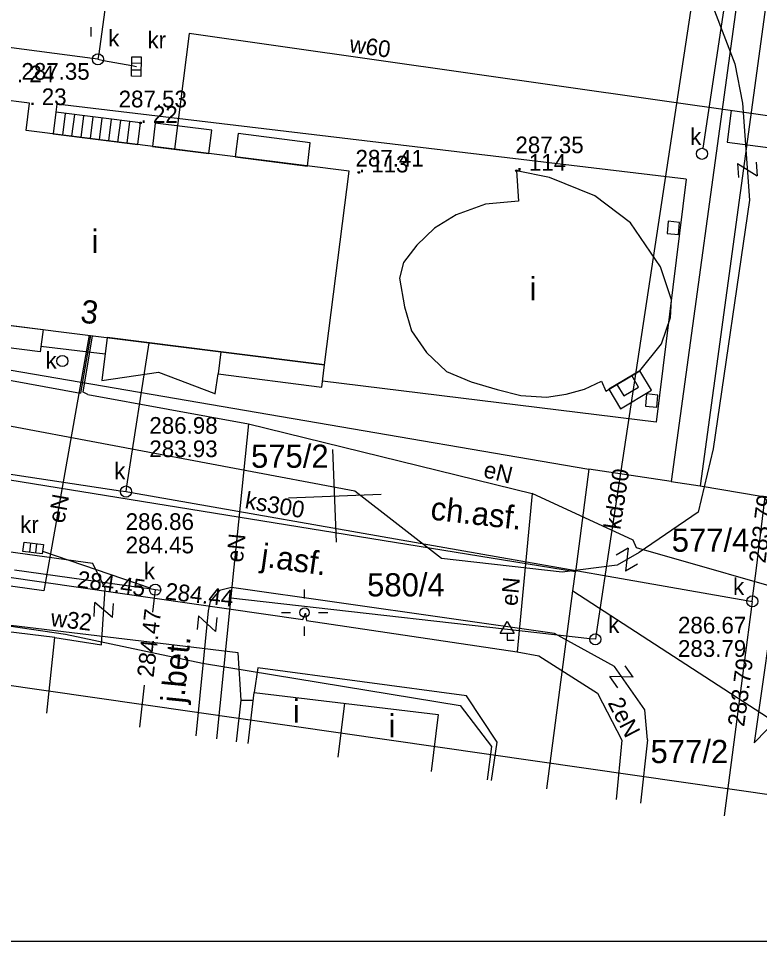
# Model space of a CAD drawing. Extents: x 4632591 to 4651936, y 5351032 to 5369988.
# Drawn here: x 4642770.86 to 4642810.82, y 5360025.34 to 5360075.11 of the extents above; entities that cross this region are included whole.
import ezdxf

# ---------------------------------------------------------------- set-up
doc = ezdxf.new("R2010")
doc.units = 0
for name, color, linetype in [('EADPD_238', 7, 'Continuous'), ('EBUPO_314', 7, 'Continuous'), ('EBUPP_312', 7, 'Continuous'), ('EBUPP_316', 7, 'Continuous'), ('EDTTS_991', 7, 'Continuous'), ('EDZPD_211', 7, 'Continuous'), ('EDZPD_219', 7, 'Continuous'), ('SDRPK_422', 7, 'Continuous'), ('SDRPK_423', 7, 'Continuous'), ('SDRPK_432', 7, 'Continuous'), ('SDRPZ_407', 7, 'Continuous'), ('UEEPA_510', 7, 'Continuous'), ('UEEPO_585', 7, 'Continuous'), ('UEETA_515', 7, 'Continuous'), ('UKKPA_506', 7, 'Continuous'), ('UKKPA_509', 7, 'Continuous'), ('UKKPO_582', 7, 'Continuous'), ('UWWPO_581', 7, 'Continuous'), ('Warstwa 40', 7, 'Continuous'), ('Warstwa 50', 7, 'Continuous'), ('Warstwa 62', 7, 'Continuous'), ('WUKPS_403', 7, 'Continuous')]:
    doc.layers.add(name, color=color, linetype=linetype)

msp = doc.modelspace()

# ---------------------------------------------------------------- linework, layer by layer
at = {"layer": 'EBUPO_314'}
for points in [[(4642806.854, 5360066.446), (4642772.935, 5360070.496), (4642772.882, 5360070.055)], [(4642806.854, 5360066.446), (4642805.234, 5360053.335), (4642787.255, 5360055.555)], [(4642775.531, 5360057.003), (4642772.073, 5360057.43)]]:
    msp.add_lwpolyline(points, dxfattribs=at)
at = {"layer": 'EBUPP_312'}
for p, q in [((4642771.462, 5360070.537), (4642765.12, 5360071.336)), ((4642771.277, 5360069.068), (4642771.462, 5360070.537)), ((4642788.682, 5360066.873), (4642771.277, 5360069.068)), ((4642787.365, 5360056.43), (4642788.682, 5360066.873)), ((4642769.194, 5360058.721), (4642787.365, 5360056.43))]:
    msp.add_line(p, q, dxfattribs=at)
for points in [[(4642867.168, 5360325.869), (4642867.168, 5360025.339), (4642701.152, 5360025.339), (4642701.152, 5360349.707), (4642867.168, 5360349.707), (4642867.168, 5360324.166)], [(4642772.396, 5360037.653), (4642772.817, 5360041.74), (4642764.24, 5360042.78), (4642763.711, 5360038.969)]]:
    msp.add_lwpolyline(points, dxfattribs=at)
for points in [[(4642797.71, 5360066.9), (4642797.816, 5360065.261), (4642796.034, 5360065.101), (4642794.464, 5360064.516), (4642793.293, 5360063.797), (4642792.336, 5360062.893), (4642791.617, 5360061.962), (4642791.404, 5360061.11), (4642791.67, 5360059.567), (4642792.043, 5360058.264), (4642792.868, 5360057.093), (4642793.932, 5360056.082), (4642795.262, 5360055.523), (4642796.672, 5360055.098), (4642797.949, 5360054.778), (4642799.333, 5360054.699), (4642800.397, 5360054.858), (4642801.381, 5360055.124), (4642802.286, 5360055.55), (4642802.525, 5360055.018), (4642804.361, 5360056.109), (4642805.532, 5360057.572), (4642806.011, 5360058.982), (4642806.064, 5360059.94), (4642805.478, 5360061.722), (4642803.856, 5360064.09), (4642801.94, 5360065.553), (4642799.492, 5360066.538)], [(4642805.829, 5360063.513), (4642806.439, 5360063.455), (4642806.501, 5360064.116), (4642805.891, 5360064.173)], [(4642804.665, 5360054.202), (4642805.275, 5360054.145), (4642805.337, 5360054.806), (4642804.727, 5360054.863)]]:
    msp.add_lwpolyline(points, close=True, dxfattribs=at)
at = {"layer": 'EBUPP_316'}
for p, q in [((4642772.882, 5360070.055), (4642772.735, 5360068.884)), ((4642777.44, 5360069.48), (4642772.882, 5360070.055)), ((4642773.378, 5360069.992), (4642773.231, 5360068.821)), ((4642773.874, 5360069.93), (4642773.727, 5360068.759)), ((4642774.37, 5360069.867), (4642774.223, 5360068.696)), ((4642774.866, 5360069.804), (4642774.719, 5360068.634)), ((4642775.363, 5360069.742), (4642775.215, 5360068.571)), ((4642775.859, 5360069.679), (4642775.711, 5360068.509)), ((4642776.355, 5360069.617), (4642776.207, 5360068.446)), ((4642776.851, 5360069.554), (4642776.703, 5360068.383)), ((4642777.292, 5360068.309), (4642777.44, 5360069.48)), ((4642772.735, 5360068.884), (4642777.292, 5360068.309)), ((4642804.361, 5360056.109), (4642802.696, 5360055.119)), ((4642804.298, 5360055.235), (4642803.931, 5360055.853)), ((4642804.984, 5360055.061), (4642804.361, 5360056.109)), ((4642803.126, 5360055.375), (4642803.493, 5360054.757)), ((4642803.493, 5360054.757), (4642804.298, 5360055.235)), ((4642802.696, 5360055.119), (4642803.318, 5360054.071)), ((4642803.318, 5360054.071), (4642804.984, 5360055.061)), ((4642783.238, 5360036.01), (4642783.573, 5360038.775)), ((4642783.573, 5360038.775), (4642793.488, 5360037.576)), ((4642788.098, 5360035.274), (4642788.451, 5360038.185)), ((4642793.488, 5360037.576), (4642793.117, 5360034.513))]:
    msp.add_line(p, q, dxfattribs=at)
for points in [[(4642778.079, 5360068.21), (4642781.131, 5360067.825), (4642781.29, 5360069.086), (4642778.238, 5360069.471)], [(4642782.553, 5360067.646), (4642786.438, 5360067.156), (4642786.596, 5360068.41), (4642782.711, 5360068.9)], [(4642769.194, 5360058.721), (4642772.188, 5360058.344), (4642772.036, 5360057.139), (4642769.042, 5360057.517)], [(4642787.365, 5360056.43), (4642781.773, 5360057.135), (4642781.623, 5360055.941), (4642787.215, 5360055.236)]]:
    msp.add_lwpolyline(points, close=True, dxfattribs=at)
msp.add_lwpolyline([(4642781.773, 5360057.135), (4642775.646, 5360057.908), (4642775.353, 5360055.591), (4642778.413, 5360056.044), (4642781.393, 5360054.9), (4642781.466, 5360054.873), (4642781.623, 5360055.941)], dxfattribs=at)
at = {"layer": 'EDTTS_991'}
for p, q in [((4642809.63, 5360067.293), (4642809.685, 5360066.545)), ((4642809.63, 5360067.293), (4642810.682, 5360066.619)), ((4642810.627, 5360067.367), (4642810.682, 5360066.619)), ((4642803.728, 5360046.549), (4642803.082, 5360046.167)), ((4642803.728, 5360046.549), (4642803.591, 5360045.306)), ((4642804.237, 5360045.688), (4642803.591, 5360045.306)), ((4642774.938, 5360042.873), (4642774.984, 5360043.621)), ((4642775.936, 5360042.812), (4642774.984, 5360043.621)), ((4642775.936, 5360042.812), (4642775.982, 5360043.56)), ((4642780.562, 5360042.909), (4642780.488, 5360042.163)), ((4642780.562, 5360042.909), (4642781.483, 5360042.064)), ((4642781.557, 5360042.81), (4642781.483, 5360042.064)), ((4642804.001, 5360039.6), (4642803.569, 5360040.213)), ((4642803.184, 5360039.024), (4642802.752, 5360039.637)), ((4642804.001, 5360039.6), (4642802.752, 5360039.637))]:
    msp.add_line(p, q, dxfattribs=at)
at = {"layer": 'EDZPD_219'}
for p, q in [((4642824.477, 5360185.186), (4642806.059, 5360050.143)), ((4642825.78, 5360183.06), (4642807.62, 5360049.911)), ((4642751.632, 5360059.37), (4642801.611, 5360050.804)), ((4642800.891, 5360045.282), (4642744.86, 5360054.352)), ((4642801.611, 5360050.804), (4642800.891, 5360045.282)), ((4642806.059, 5360050.143), (4642801.611, 5360050.804)), ((4642806.059, 5360050.143), (4642807.62, 5360049.911)), ((4642807.62, 5360049.911), (4642815.357, 5360048.606)), ((4642736.141, 5360047.388), (4642773.396, 5360041.921)), ((4642736.141, 5360047.388), (4642773.396, 5360041.921)), ((4642800.756, 5360044.241), (4642800.891, 5360045.282)), ((4642799.351, 5360033.568), (4642800.756, 5360044.241)), ((4642800.756, 5360044.241), (4642814.236, 5360035.496)), ((4642773.396, 5360041.921), (4642780.783, 5360040.343)), ((4642773.396, 5360041.921), (4642773.396, 5360041.921)), ((4642773.396, 5360041.921), (4642780.783, 5360040.343)), ((4642780.783, 5360040.343), (4642794.682, 5360038.062)), ((4642780.783, 5360040.343), (4642794.682, 5360038.062)), ((4642794.682, 5360038.062), (4642796.37, 5360035.857)), ((4642794.682, 5360038.062), (4642796.37, 5360035.857)), ((4642796.37, 5360035.857), (4642796.126, 5360034.057)), ((4642796.37, 5360035.857), (4642796.126, 5360034.057))]:
    msp.add_line(p, q, dxfattribs=at)
at = {"layer": 'SDRPK_422'}
for p, q in [((4642772.817, 5360041.74), (4642775.345, 5360041.341)), ((4642780.852, 5360040.782), (4642780.423, 5360036.437)), ((4642804.77, 5360036.206), (4642804.406, 5360032.802))]:
    msp.add_line(p, q, dxfattribs=at)
for points in [[(4642818.214, 5360091.65), (4642811.81, 5360045.043), (4642810.533, 5360036.05), (4642813.886, 5360039.505)], [(4642804.17, 5360081.76), (4642805.635, 5360080.025), (4642807.058, 5360077.963), (4642808.388, 5360075.529), (4642809.479, 5360072.669), (4642809.892, 5360070.54), (4642810.277, 5360065.312), (4642808.309, 5360051.903), (4642807.51, 5360048.498), (4642804.318, 5360046.316), (4642803.147, 5360045.625), (4642800.167, 5360045.252), (4642793.676, 5360045.997), (4642788.993, 5360049.615), (4642769.518, 5360053.287), (4642764.35, 5360050.83)], [(4642775.345, 5360041.341), (4642775.531, 5360044.374), (4642774.866, 5360045.731), (4642762.08, 5360047.48), (4642736.421, 5360051.638)], [(4642804.77, 5360036.206), (4642804.637, 5360037.829), (4642802.988, 5360040.171), (4642799.768, 5360041.953), (4642782.342, 5360044.427), (4642781.704, 5360044.268), (4642781.198, 5360043.682), (4642781.092, 5360043.177), (4642780.852, 5360040.782)]]:
    msp.add_lwpolyline(points, dxfattribs=at)
at = {"layer": 'SDRPK_423'}
msp.add_lwpolyline([(4642796.367, 5360034.021), (4642796.662, 5360036.085), (4642795.013, 5360038.586), (4642783.759, 5360040.102), (4642783.573, 5360038.772)], dxfattribs=at)
at = {"layer": 'SDRPZ_407'}
for p, q in [((4642797.213, 5360041.941), (4642797.213, 5360041.591)), ((4642797.213, 5360041.591), (4642797.588, 5360041.591))]:
    msp.add_line(p, q, dxfattribs=at)
msp.add_lwpolyline([(4642796.838, 5360041.941), (4642797.213, 5360042.591), (4642797.588, 5360041.941)], close=True, dxfattribs=at)
at = {"layer": 'UEEPA_510'}
msp.add_circle((4642786.285, 5360043.077), 0.25, dxfattribs=at)
at = {"layer": 'UEEPO_585'}
for p, q in [((4642774.752, 5360058.02), (4642774.214, 5360054.913)), ((4642783.258, 5360053.26), (4642798.55, 5360049.502)), ((4642773.112, 5360049.211), (4642772.838, 5360047.668)), ((4642782.637, 5360047.091), (4642782.479, 5360045.532))]:
    msp.add_line(p, q, dxfattribs=at)
for points in [[(4642774.678, 5360058.03), (4642773.112, 5360049.211)], [(4642774.596, 5360054.843), (4642774.347, 5360054.953), (4642774.859, 5360058.007)], [(4642767.437, 5360056.152), (4642774.214, 5360054.913)], [(4642774.596, 5360054.843), (4642783.258, 5360053.26), (4642782.637, 5360047.091)], [(4642823.159, 5360042.478), (4642813.981, 5360043.755), (4642804.177, 5360046.576), (4642804.004, 5360046.975), (4642798.55, 5360049.502), (4642797.752, 5360040.962), (4642798.922, 5360040.749), (4642802.088, 5360038.727), (4642803.392, 5360036.2), (4642803.077, 5360033.004)], [(4642772.838, 5360047.668), (4642772.231, 5360044.248), (4642750.361, 5360047.307), (4642744.971, 5360048.421)], [(4642766.104, 5360045.603), (4642786.198, 5360042.704), (4642786.247, 5360042.83)], [(4642782.479, 5360045.532), (4642781.545, 5360036.267)], [(4642786.247, 5360042.83), (4642786.331, 5360043.05), (4642786.36, 5360042.839)], [(4642786.36, 5360042.839), (4642786.385, 5360042.651), (4642797.752, 5360040.962)]]:
    msp.add_lwpolyline(points, dxfattribs=at)
at = {"layer": 'UEETA_515'}
for p, q in [((4642774.78, 5360074.14), (4642774.78, 5360074.64)), ((4642786.285, 5360043.827), (4642786.285, 5360044.327)), ((4642785.035, 5360043.077), (4642785.535, 5360043.077)), ((4642787.035, 5360043.077), (4642787.535, 5360043.077)), ((4642786.285, 5360041.827), (4642786.285, 5360042.327))]:
    msp.add_line(p, q, dxfattribs=at)
at = {"layer": 'UKKPA_506'}
for centre in [(4642775.145, 5360072.908), (4642807.71, 5360067.813), (4642773.23, 5360056.639), (4642776.662, 5360049.602), (4642778.232, 5360044.308), (4642810.424, 5360043.682), (4642801.963, 5360041.634)]:
    msp.add_circle(centre, 0.3, dxfattribs=at)
at = {"layer": 'UKKPA_509'}
for p, q in [((4642777.474, 5360072.691), (4642776.974, 5360072.7)), ((4642776.967, 5360072.35), (4642777.467, 5360072.341)), ((4642771.508, 5360046.828), (4642771.449, 5360046.332)), ((4642771.797, 5360046.291), (4642771.855, 5360046.788))]:
    msp.add_line(p, q, dxfattribs=at)
for points in [[(4642776.961, 5360072), (4642776.981, 5360073.05), (4642777.48, 5360073.041), (4642777.461, 5360071.991)], [(4642771.16, 5360046.869), (4642772.203, 5360046.747), (4642772.145, 5360046.25), (4642771.102, 5360046.373)]]:
    msp.add_lwpolyline(points, close=True, dxfattribs=at)
at = {"layer": 'UKKPO_582'}
for p, q in [((4642803.338, 5360050.72), (4642802.818, 5360047.283)), ((4642810.627, 5360045.321), (4642811.124, 5360049.331)), ((4642772.16, 5360046.386), (4642777.948, 5360044.405)), ((4642777.605, 5360044.395), (4642773.604, 5360044.956)), ((4642810.008, 5360040.517), (4642809.481, 5360036.511))]:
    msp.add_line(p, q, dxfattribs=at)
for points in [[(4642813.038, 5360103.272), (4642807.754, 5360068.11)], [(4642779.22, 5360102.831), (4642775.186, 5360073.205)], [(4642807.811, 5360080.274), (4642803.338, 5360050.72)], [(4642774.848, 5360072.947), (4642769.777, 5360073.62)], [(4642775.186, 5360073.205), (4642775.145, 5360072.908), (4642775.44, 5360072.853)], [(4642775.145, 5360072.908), (4642774.848, 5360072.947)], [(4642775.44, 5360072.853), (4642776.971, 5360072.567)], [(4642776.971, 5360072.567), (4642777.221, 5360072.521)], [(4642776.708, 5360049.898), (4642777.903, 5360057.623)], [(4642761.765, 5360051.846), (4642776.366, 5360049.647)], [(4642776.366, 5360049.647), (4642776.662, 5360049.602), (4642776.708, 5360049.898)], [(4642776.662, 5360049.602), (4642776.956, 5360049.55)], [(4642776.956, 5360049.55), (4642810.128, 5360043.734)], [(4642802.818, 5360047.283), (4642802.008, 5360041.93)], [(4642773.604, 5360044.956), (4642770.652, 5360045.369)], [(4642810.461, 5360043.98), (4642810.627, 5360045.321)], [(4642777.935, 5360044.349), (4642777.605, 5360044.395)], [(4642778.232, 5360044.308), (4642777.935, 5360044.349)], [(4642778.528, 5360044.274), (4642778.232, 5360044.308), (4642778.198, 5360044.01)], [(4642778.198, 5360044.01), (4642778.094, 5360043.099)], [(4642801.665, 5360041.667), (4642782.319, 5360043.847)], [(4642810.128, 5360043.734), (4642810.424, 5360043.682), (4642810.385, 5360043.385)], [(4642810.424, 5360043.682), (4642810.461, 5360043.98)], [(4642810.385, 5360043.385), (4642810.008, 5360040.517)], [(4642802.008, 5360041.93), (4642801.963, 5360041.634), (4642801.665, 5360041.667)], [(4642777.647, 5360039.157), (4642777.39, 5360036.896)], [(4642809.481, 5360036.511), (4642808.904, 5360032.121)]]:
    msp.add_lwpolyline(points, dxfattribs=at)
at = {"layer": 'UWWPO_581'}
for points in [[(4642815.287, 5360031.154), (4642820.219, 5360068.578), (4642780.073, 5360074.298), (4642779.279, 5360068.059)], [(4642782.866, 5360038.355), (4642782.706, 5360040.909), (4642764.748, 5360043.064), (4642765.759, 5360050.114), (4642737.013, 5360055.431)], [(4642782.613, 5360036.105), (4642782.866, 5360038.355), (4642783.522, 5360038.355)]]:
    msp.add_lwpolyline(points, dxfattribs=at)
at = {"layer": 'Warstwa 40'}
for p, q in [((4642809.288, 5360070.148), (4642809.076, 5360068.446)), ((4642809.076, 5360068.446), (4642830.679, 5360065.519)), ((4642737.557, 5360043.881), (4642823.333, 5360031.534))]:
    msp.add_line(p, q, dxfattribs=at)
at = {"layer": 'Warstwa 50'}
for p, q in [((4642788.013, 5360046.868), (4642787.815, 5360051.864)), ((4642785.416, 5360049.267), (4642790.412, 5360049.465))]:
    msp.add_line(p, q, dxfattribs=at)
at = {"layer": 'WUKPS_403'}
for centre in [(4642777.44, 5360069.48), (4642789.21, 5360066.81), (4642797.71, 5360066.9)]:
    msp.add_circle(centre, 0.045, dxfattribs=at)

# ---------------------------------------------------------------- texts
at = {"layer": 'EADPD_238'}
msp.add_text('3', height=1.25, rotation=352.825, dxfattribs=at).set_placement((4642774.156, 5360058.725))
at = {"layer": 'EBUPP_316'}
for p in [(4642774.798, 5360062.47), (4642798.423, 5360059.916), (4642785.653, 5360037.142), (4642790.814, 5360036.344)]:
    msp.add_text('i', height=1.25, dxfattribs=at).set_placement(p)
at = {"layer": 'EDZPD_211'}
for s, p in [('575/2', (4642783.4, 5360050.884)), ('577/4', (4642806.082, 5360046.357)), ('580/4', (4642789.659, 5360043.947)), ('577/2', (4642804.939, 5360034.961))]:
    msp.add_text(s, height=1.25, dxfattribs=at).set_placement(p)
at = {"layer": 'SDRPK_432'}
for s, rotation, p in [('ch.asf.', 353.4537, (4642793.036, 5360048.096)), ('j.asf.', 351.9189, (4642783.884, 5360045.569)), ('j.bet.', 84.3584, (4642779.787, 5360038.159))]:
    msp.add_text(s, height=1.25, rotation=rotation, dxfattribs=at).set_placement(p)
at = {"layer": 'UEEPO_585'}
for s, rotation, p in [('eN', 346.1883, (4642795.875, 5360050.391)), ('eN', 79.9276, (4642773.329, 5360047.855)), ('eN', 84.2404, (4642782.955, 5360045.756)), ('eN', 84.6547, (4642797.754, 5360043.406)), ('2eN', 297.2571, (4642802.608, 5360038.213))]:
    msp.add_text(s, height=0.9, rotation=rotation, dxfattribs=at).set_placement(p)
at = {"layer": 'UKKPA_506'}
for s, p in [('k', (4642775.704, 5360073.6)), ('kr', (4642777.817, 5360073.502)), ('k', (4642807.071, 5360068.292)), ('k', (4642772.325, 5360056.227)), ('286.98', (4642777.918, 5360052.719)), ('283.93', (4642777.918, 5360051.459)), ('k', (4642776.023, 5360050.267)), ('kr', (4642770.953, 5360047.376)), ('286.86', (4642776.641, 5360047.531)), ('284.45', (4642776.641, 5360046.271)), ('k', (4642777.62, 5360044.866)), ('k', (4642809.386, 5360044.028)), ('k', (4642802.655, 5360041.98)), ('286.67', (4642806.418, 5360041.95)), ('283.79', (4642806.418, 5360040.69))]:
    msp.add_text(s, height=0.9, dxfattribs=at).set_placement(p)
at = {"layer": 'UKKPO_582'}
for s, rotation, p in [('kd300', 81.3924, (4642803.309, 5360047.519)), ('ks300', 350.0532, (4642783.029, 5360048.715)), ('283.79', 82.9324, (4642811.13, 5360045.712)), ('284.45', 352.0305, (4642773.987, 5360044.449)), ('284.44', 353.5744, (4642778.74, 5360043.798)), ('284.44', 353.5744, (4642778.74, 5360043.797)), ('284.47', 83.5226, (4642778.145, 5360039.554)), ('284.47', 83.5156, (4642778.145, 5360039.554)), ('283.79', 82.5093, (4642809.986, 5360036.898))]:
    msp.add_text(s, height=0.9, rotation=rotation, dxfattribs=at).set_placement(p)
at = {"layer": 'UWWPO_581'}
for s, rotation, p in [('w60', 351.8928, (4642788.668, 5360073.301)), ('w32', 353.1607, (4642772.566, 5360042.353))]:
    msp.add_text(s, height=0.9, rotation=rotation, dxfattribs=at).set_placement(p)
at = {"layer": 'Warstwa 62'}
for s, p in [('. 24', (4642770.78, 5360071.67)), ('. 23', (4642771.45, 5360070.44)), ('. 22', (4642777.44, 5360069.48)), ('. 113', (4642789.21, 5360066.81)), ('. 114', (4642797.71, 5360066.9))]:
    msp.add_text(s, height=0.9, dxfattribs=at).set_placement(p)
at = {"layer": 'WUKPS_403'}
for s, p in [('287.35', (4642771.02, 5360071.808)), ('287.53', (4642776.262, 5360070.318)), ('287.35', (4642797.652, 5360067.844)), ('287.41', (4642789.032, 5360067.125))]:
    msp.add_text(s, height=0.9, dxfattribs=at).set_placement(p)

doc.saveas('drawing.dxf')
